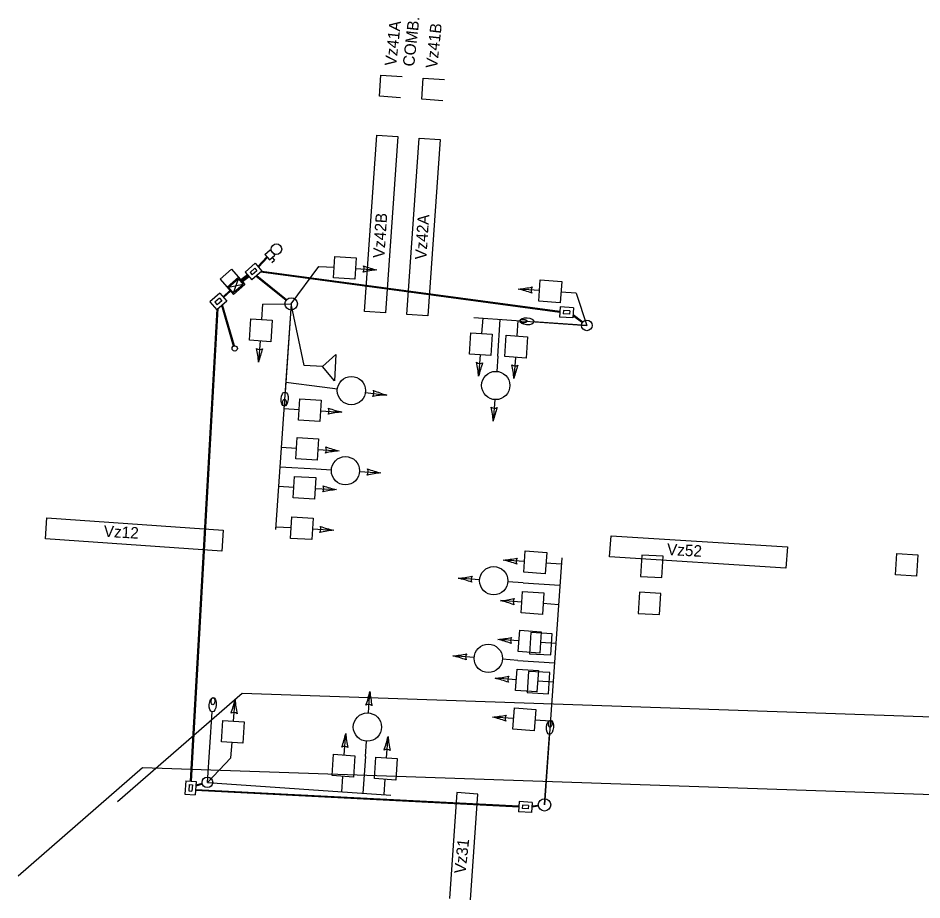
# Model space of a CAD drawing. Extents: x 647787 to 668496, y 640478 to 654412.
# Drawn here: x 661051 to 661306.8, y 647262.5 to 647511.9 of the extents above; entities that cross this region are included whole.
import ezdxf

# ---------------------------------------------------------------- set-up
doc = ezdxf.new("R2010")
doc.units = 0
for name, color, linetype in [('Default', 7, 'Continuous'), ('TEMP_DETECTION ZONE', 7, 'Continuous'), ('TEMP_DETECTION ZONE_STAGE 3', 7, 'Continuous'), ('TEMP_SIGNAL_HEAD_STAGE 1A', 7, 'Continuous'), ('TEMP_SIGNAL_POLES_STAGE 1A', 7, 'Continuous'), ('TEMP_SIGNAL_POLES_STAGE 1B', 7, 'Continuous'), ('TEXT_TEMP_SIGNAL_POLES_STAGE 5', 7, 'Continuous')]:
    doc.layers.add(name, color=color, linetype=linetype)

msp = doc.modelspace()

# ---------------------------------------------------------------- linework, layer by layer
at = {"layer": 'Default'}
for p, q in [((661114.4, 647320.89), (661079.2, 647290.26)), ((661086.25, 647299.89), (661051.05, 647269.26))]:
    msp.add_line(p, q, dxfattribs=at)
for points in [[(662136.44, 647331.77), (661882.02, 647294.61), (661114.4, 647320.89)], [(662108.29, 647310.77), (661853.87, 647273.61), (661086.25, 647299.89)]]:
    msp.add_lwpolyline(points, dxfattribs=at)
at = {"layer": 'TEMP_DETECTION ZONE'}
for points in [[(661227.5, 647359.98), (661227.14, 647354), (661233.13, 647353.68), (661233.5, 647359.67)], [(661227.5, 647359.98), (661227.14, 647354), (661233.13, 647353.68), (661233.5, 647359.67)], [(661226.87, 647349.5), (661226.51, 647343.51), (661232.5, 647343.2), (661232.86, 647349.19)], [(661226.87, 647349.5), (661226.51, 647343.51), (661232.5, 647343.2), (661232.86, 647349.19)]]:
    msp.add_lwpolyline(points, close=True, dxfattribs=at)
at = {"layer": 'TEMP_DETECTION ZONE_STAGE 3'}
for points in [[(661196.13, 647338.09), (661195.77, 647332.1), (661201.76, 647331.79), (661202.12, 647337.77)], [(661196.13, 647338.09), (661195.77, 647332.1), (661201.76, 647331.79), (661202.12, 647337.77)], [(661196.13, 647338.09), (661195.77, 647332.1), (661201.76, 647331.79), (661202.12, 647337.77)], [(661196.13, 647338.09), (661195.77, 647332.1), (661201.76, 647331.79), (661202.12, 647337.78)], [(661195.46, 647327.11), (661195.1, 647321.12), (661201.09, 647320.81), (661201.46, 647326.79)], [(661195.46, 647327.11), (661195.1, 647321.12), (661201.09, 647320.81), (661201.46, 647326.79)], [(661195.46, 647327.11), (661195.1, 647321.12), (661201.09, 647320.81), (661201.46, 647326.79)], [(661195.47, 647327.11), (661195.11, 647321.12), (661201.1, 647320.81), (661201.46, 647326.8)]]:
    msp.add_lwpolyline(points, close=True, dxfattribs=at)
at = {"layer": 'TEMP_SIGNAL_HEAD_STAGE 1A'}
for p, q in [((661120.84, 647444.99), (661122.35, 647446.31)), ((661122.35, 647446.31), (661123.66, 647444.8)), ((661118.89, 647441.61), (661121.41, 647444.34)), ((661119.05, 647441.42), (661121.58, 647444.15)), ((661120.84, 647444.99), (661122.15, 647443.49)), ((661122.15, 647443.49), (661123.66, 647444.8)), ((661122.81, 647442.73), (661123.56, 647443.39)), ((661122.91, 647444.14), (661123.56, 647443.39)), ((661118.09, 647442.53), (661115.26, 647440.07)), ((661117.99, 647441.12), (661116.67, 647439.97)), ((661120, 647440.33), (661117.17, 647437.87)), ((661118.59, 647440.43), (661117.27, 647439.28)), ((661117.99, 647441.12), (661118.59, 647440.43)), ((661118.09, 647442.53), (661120, 647440.33)), ((661119.97, 647440.31), (661204.34, 647428.98)), ((661115.94, 647439.29), (661114.09, 647437.83)), ((661116.1, 647439.1), (661114.25, 647437.64)), ((661116.26, 647438.91), (661114.42, 647437.45)), ((661116.43, 647438.72), (661114.58, 647437.26)), ((661115.26, 647440.07), (661117.17, 647437.87)), ((661116.67, 647439.97), (661117.27, 647439.28)), ((661118.38, 647438.92), (661126.87, 647432.06)), ((661118.57, 647439.09), (661127.03, 647432.26)), ((661119.72, 647440.09), (661204.33, 647428.73)), ((661108.16, 647434.07), (661105.33, 647431.61)), ((661108.06, 647432.66), (661106.74, 647431.51)), ((661108.06, 647432.66), (661108.67, 647431.96)), ((661108.16, 647434.07), (661110.08, 647431.87)), ((661110.98, 647434.81), (661109.03, 647433.07)), ((661111.06, 647434.71), (661109.11, 647432.98)), ((661111.14, 647434.62), (661109.19, 647432.88)), ((661105.33, 647431.61), (661107.25, 647429.41)), ((661106.74, 647431.51), (661107.35, 647430.82)), ((661110.08, 647431.87), (661107.25, 647429.41)), ((661108.67, 647431.96), (661107.35, 647430.82)), ((661112, 647419.13), (661108.66, 647430.63)), ((661112.24, 647419.2), (661108.87, 647430.81)), ((661204.43, 647430.24), (661204.23, 647427.33)), ((661208.17, 647429.98), (661204.43, 647430.24)), ((661208.17, 647429.98), (661207.97, 647427.07)), ((661099.82, 647296.08), (661107.4, 647429.54)), ((661100.07, 647296.07), (661107.66, 647429.77)), ((661205.36, 647429.17), (661205.3, 647428.26)), ((661207.04, 647428.14), (661205.3, 647428.26)), ((661207.11, 647429.05), (661205.36, 647429.17)), ((661207.11, 647429.05), (661207.04, 647428.14)), ((661208.02, 647427.74), (661210.68, 647425.76)), ((661208.04, 647428.04), (661210.83, 647425.96)), ((661207.97, 647427.07), (661204.23, 647427.33)), ((661098.5, 647296.18), (661098.24, 647292.44)), ((661098.5, 647296.18), (661101.41, 647295.97)), ((661099.43, 647295.11), (661099.31, 647293.36)), ((661099.43, 647295.11), (661100.35, 647295.05)), ((661100.35, 647295.05), (661100.22, 647293.3)), ((661101.41, 647295.97), (661101.15, 647292.23)), ((661103.2, 647295.23), (661101.32, 647294.7)), ((661103.13, 647295.47), (661101.34, 647294.97)), ((661098.24, 647292.44), (661101.15, 647292.23)), ((661099.31, 647293.36), (661100.22, 647293.3)), ((661192.67, 647288.77), (661101.24, 647293.43)), ((661192.69, 647289.02), (661101.25, 647293.68)), ((661192.78, 647290.36), (661192.58, 647287.45)), ((661196.52, 647290.1), (661192.78, 647290.36)), ((661196.52, 647290.1), (661196.32, 647287.19)), ((661196.32, 647287.19), (661192.58, 647287.45)), ((661193.71, 647289.3), (661193.65, 647288.38)), ((661195.39, 647288.26), (661193.65, 647288.38)), ((661195.46, 647289.18), (661193.71, 647289.3)), ((661195.46, 647289.18), (661195.39, 647288.26)), ((661198.27, 647289), (661196.43, 647288.74)), ((661198.24, 647289.25), (661196.45, 647288.99))]:
    msp.add_line(p, q, dxfattribs=at)
for centre, radius in [((661124.14, 647446.54), 1.5), ((661112.33, 647418.45), 0.75)]:
    msp.add_circle(centre, radius, dxfattribs=at)
at = {"layer": 'TEMP_SIGNAL_POLES_STAGE 1A'}
for p, q in [((661128.31, 647431.06), (661136.15, 647441.67)), ((661136.15, 647441.67), (661140.49, 647441.41)), ((661146.54, 647441.05), (661152.57, 647440.68)), ((661198.58, 647434.83), (661192.55, 647435.25)), ((661208.96, 647434.11), (661204.63, 647434.41)), ((661208.96, 647434.11), (661211.95, 647424.97)), ((661120.23, 647430.95), (661119.93, 647426.62)), ((661120.23, 647430.95), (661128.31, 647431.06)), ((661128.31, 647431.06), (661123.87, 647367.22)), ((661128.31, 647431.06), (661126.57, 647406.12)), ((661131.95, 647413.65), (661128.31, 647431.06)), ((661180.03, 647427.19), (661211.95, 647424.97)), ((661182.49, 647427.02), (661182.19, 647422.68)), ((661186.76, 647416.29), (661187.48, 647426.67)), ((661192.47, 647426.33), (661192.16, 647421.99)), ((661211.95, 647424.97), (661196.99, 647426.01)), ((661119.51, 647420.57), (661119.09, 647414.54)), ((661181.77, 647416.64), (661181.35, 647410.61)), ((661186.76, 647416.29), (661186.45, 647411.97)), ((661191.74, 647415.94), (661191.32, 647409.92)), ((661126.77, 647408.88), (661137.08, 647407.58)), ((661137.08, 647407.58), (661141.38, 647407.03)), ((661149.31, 647406.03), (661155.33, 647405.27)), ((661185.9, 647403.99), (661185.48, 647397.94)), ((661126.25, 647401.46), (661130.59, 647401.2)), ((661136.64, 647400.84), (661142.67, 647400.47)), ((661125.49, 647390.49), (661129.83, 647390.23)), ((661135.88, 647389.86), (661141.91, 647389.5)), ((661125.06, 647385.01), (661135.36, 647384.38)), ((661135.36, 647384.38), (661139.68, 647384.12)), ((661147.67, 647383.64), (661153.72, 647383.28)), ((661124.72, 647379.52), (661129.06, 647379.25)), ((661135.12, 647378.89), (661141.14, 647378.53)), ((661123.93, 647368.04), (661128.27, 647367.78)), ((661134.32, 647367.42), (661140.35, 647367.05)), ((661194.33, 647358.18), (661188.31, 647358.6)), ((661204.72, 647357.46), (661200.38, 647357.76)), ((661181.62, 647353.05), (661175.57, 647353.47)), ((661193.92, 647352.19), (661189.6, 647352.49)), ((661193.92, 647352.19), (661204.3, 647351.47)), ((661193.54, 647346.71), (661187.51, 647347.13)), ((661203.92, 647345.98), (661199.58, 647346.29)), ((661192.77, 647335.73), (661186.75, 647336.15)), ((661203.16, 647335.01), (661198.82, 647335.31)), ((661180.09, 647331.1), (661174.04, 647331.52)), ((661192.39, 647330.25), (661188.07, 647330.55)), ((661192.39, 647330.25), (661202.78, 647329.52)), ((661192.01, 647324.76), (661185.98, 647325.18)), ((661202.39, 647324.04), (661198.06, 647324.34)), ((661150.17, 647315.38), (661150.59, 647321.43)), ((661112, 647313.07), (661112.42, 647319.09)), ((661104.6, 647295.75), (661105.99, 647315.7)), ((661191.25, 647313.79), (661185.22, 647314.2)), ((661201.63, 647313.06), (661197.3, 647313.37)), ((661143.33, 647303.5), (661143.75, 647309.52)), ((661149.31, 647303.08), (661149.61, 647307.4)), ((661155.3, 647302.66), (661155.72, 647308.69)), ((661199.98, 647289.37), (661201.37, 647309.32)), ((661111.28, 647302.68), (661111.58, 647307.02)), ((661111.28, 647302.68), (661104.6, 647295.75)), ((661149.31, 647303.08), (661148.59, 647292.69)), ((661142.61, 647293.11), (661142.91, 647297.45)), ((661104.6, 647295.75), (661156.48, 647292.15)), ((661154.58, 647292.28), (661154.88, 647296.61))]:
    msp.add_line(p, q, dxfattribs=at)
for points in [[(661140.31, 647438.38), (661140.68, 647444.44), (661146.73, 647444.07), (661146.36, 647438.02)], [(661204.84, 647437.43), (661204.42, 647431.38), (661198.37, 647431.8), (661198.79, 647437.85)], [(661116.9, 647426.83), (661122.95, 647426.41), (661122.53, 647420.36), (661116.48, 647420.78)], [(661179.16, 647422.89), (661185.21, 647422.47), (661184.79, 647416.42), (661178.74, 647416.85)], [(661189.14, 647422.2), (661195.19, 647421.78), (661194.77, 647415.73), (661188.72, 647416.15)], [(661130.41, 647398.18), (661130.77, 647404.23), (661136.82, 647403.86), (661136.46, 647397.81)], [(661129.64, 647387.2), (661130.01, 647393.26), (661136.06, 647392.89), (661135.7, 647386.84)], [(661128.88, 647376.23), (661129.25, 647382.28), (661135.3, 647381.92), (661134.93, 647375.86)], [(661128.08, 647364.75), (661128.45, 647370.81), (661134.5, 647370.44), (661134.13, 647364.39)], [(661200.59, 647360.78), (661200.17, 647354.73), (661194.12, 647355.15), (661194.54, 647361.2)], [(661199.79, 647349.31), (661199.37, 647343.26), (661193.33, 647343.68), (661193.75, 647349.73)], [(661199.03, 647338.34), (661198.61, 647332.29), (661192.56, 647332.71), (661192.98, 647338.76)], [(661198.27, 647327.36), (661197.85, 647321.31), (661191.8, 647321.73), (661192.22, 647327.78)], [(661197.51, 647316.39), (661197.09, 647310.34), (661191.04, 647310.76), (661191.46, 647316.81)], [(661114.61, 647306.81), (661108.56, 647307.23), (661108.98, 647313.28), (661115.03, 647312.86)], [(661145.93, 647297.24), (661139.88, 647297.66), (661140.3, 647303.71), (661146.35, 647303.28)], [(661157.9, 647296.4), (661151.85, 647296.82), (661152.27, 647302.87), (661158.32, 647302.45)]]:
    msp.add_lwpolyline(points, close=True, dxfattribs=at)
for points in [[(661137.16, 647413.33), (661140.97, 647416.71), (661140.53, 647409.34), (661137.16, 647413.33), (661131.95, 647413.65)], [(661204.84, 647359.2), (661199.98, 647289.37)]]:
    msp.add_lwpolyline(points, dxfattribs=at)
for centre, radius in [((661128.31, 647431.06), 1.75), ((661211.95, 647424.97), 1.5), ((661145.35, 647406.53), 4), ((661186.18, 647407.98), 4), ((661143.67, 647383.88), 4), ((661185.61, 647352.77), 4), ((661184.08, 647330.82), 4), ((661149.89, 647311.39), 4), ((661104.6, 647295.75), 1.5), ((661199.98, 647289.37), 1.75)]:
    msp.add_circle(centre, radius, dxfattribs=at)
for centre, radius, start, end in [((661147.32, 647441), 1.63, 324.7005, 28.3952), ((661155.22, 647411.33), 29.47, 95.1562, 102.8943), ((661158.73, 647469.5), 29.47, 250.2014, 257.9395), ((661190.17, 647464.62), 29.47, 274.634, 282.3721), ((661186.13, 647406.48), 29.47, 69.6792, 77.4173), ((661197.81, 647434.88), 1.63, 144.1783, 207.873), ((661119.45, 647419.8), 1.63, 234.1757, 297.8704), ((661089.71, 647412.16), 29.47, 4.6314, 12.3695), ((661147.85, 647408.12), 29.47, 159.6766, 167.4147), ((661181.71, 647415.86), 1.63, 234.1757, 297.8704), ((661151.97, 647408.23), 29.47, 4.6314, 12.3695), ((661210.11, 647404.19), 29.47, 159.6766, 167.4147), ((661191.69, 647415.17), 1.63, 234.1757, 297.8704), ((661161.95, 647407.54), 29.47, 4.6314, 12.3695), ((661220.09, 647403.49), 29.47, 159.6766, 167.4147), ((661150.11, 647405.93), 1.63, 320.9402, 24.6348), ((661156.05, 647375.81), 29.47, 91.4068, 99.1449), ((661163.36, 647433.62), 29.47, 246.4511, 254.1893), ((661185.84, 647403.19), 1.63, 234.1757, 297.8704), ((661156.1, 647395.55), 29.47, 4.6424, 12.3805), ((661137.41, 647400.79), 1.63, 324.7005, 28.3952), ((661145.32, 647371.12), 29.47, 95.1562, 102.8943), ((661148.83, 647429.29), 29.47, 250.2014, 257.9395), ((661214.24, 647391.52), 29.47, 159.6867, 167.4248), ((661136.65, 647389.82), 1.63, 324.7005, 28.3952), ((661144.56, 647360.15), 29.47, 95.1562, 102.8943), ((661148.07, 647418.32), 29.47, 250.2014, 257.9395), ((661148.46, 647383.59), 1.63, 324.6979, 28.3925), ((661159.87, 647412.1), 29.47, 250.2089, 257.947), ((661156.37, 647353.92), 29.47, 95.1646, 102.9027), ((661135.89, 647378.84), 1.63, 324.7005, 28.3952), ((661147.3, 647407.35), 29.47, 250.2014, 257.9395), ((661143.79, 647349.17), 29.47, 95.1562, 102.8943), ((661135.09, 647367.37), 1.63, 324.7005, 28.3952), ((661143, 647337.7), 29.47, 95.1562, 102.8943), ((661146.51, 647395.87), 29.47, 250.2014, 257.9395), ((661185.93, 647387.97), 29.47, 274.634, 282.3721), ((661181.89, 647329.83), 29.47, 69.6792, 77.4173), ((661193.56, 647358.23), 1.63, 144.1783, 207.873), ((661173.18, 647382.84), 29.47, 274.6424, 282.3805), ((661169.15, 647324.71), 29.47, 69.6867, 77.4248), ((661180.82, 647353.1), 1.63, 144.1757, 207.8704), ((661185.13, 647376.5), 29.47, 274.634, 282.3721), ((661181.09, 647318.36), 29.47, 69.6792, 77.4173), ((661192.76, 647346.76), 1.63, 144.1783, 207.873), ((661184.37, 647365.53), 29.47, 274.634, 282.3721), ((661180.33, 647307.39), 29.47, 69.6792, 77.4173), ((661192, 647335.79), 1.63, 144.1783, 207.873), ((661171.66, 647360.9), 29.47, 274.6424, 282.3805), ((661167.62, 647302.76), 29.47, 69.6867, 77.4248), ((661179.29, 647331.16), 1.63, 144.1757, 207.8704), ((661183.6, 647354.55), 29.47, 274.634, 282.3721), ((661179.56, 647296.41), 29.47, 69.6792, 77.4173), ((661191.24, 647324.81), 1.63, 144.1783, 207.873), ((661121.83, 647327.85), 29.47, 339.6867, 347.4248), ((661179.96, 647323.81), 29.47, 184.6424, 192.3805), ((661083.66, 647325.52), 29.47, 339.6766, 347.4147), ((661141.8, 647321.47), 29.47, 184.6314, 192.3695), ((661150.22, 647316.18), 1.63, 54.1757, 117.8704), ((661112.06, 647313.84), 1.63, 54.1757, 117.8704), ((661182.84, 647343.58), 29.47, 274.634, 282.3721), ((661178.8, 647285.44), 29.47, 69.6792, 77.4173), ((661190.47, 647313.84), 1.63, 144.1783, 207.873), ((661114.98, 647315.94), 29.47, 339.6766, 347.4147), ((661173.12, 647311.9), 29.47, 184.6314, 192.3695), ((661126.95, 647315.11), 29.47, 339.6766, 347.4147), ((661185.09, 647311.07), 29.47, 184.6314, 192.3695), ((661143.38, 647304.27), 1.63, 54.1757, 117.8704), ((661155.35, 647303.43), 1.63, 54.1757, 117.8704)]:
    msp.add_arc(centre, radius, start, end, dxfattribs=at)
for centre, major_axis in [((661194.99, 647426.15), (-2, 0.14)), ((661194, 647426.22), (0.998, -0.069)), ((661126.44, 647404.13), (-0.14, -2)), ((661126.37, 647403.13), (0.069, 0.998)), ((661106.13, 647317.7), (0.14, 2)), ((661106.2, 647318.7), (-0.069, -0.998)), ((661201.51, 647311.32), (0.14, 2)), ((661201.58, 647312.32), (-0.069, -0.998))]:
    msp.add_ellipse(centre, major_axis=major_axis, ratio=0.5, dxfattribs=at)
at = {"layer": 'TEMP_SIGNAL_POLES_STAGE 1B'}
for p, q in [((661153.27, 647489.77), (661153.69, 647495.75)), ((661153.69, 647495.75), (661159.67, 647495.33)), ((661165.24, 647488.93), (661165.66, 647494.92)), ((661165.66, 647494.92), (661171.64, 647494.5)), ((661159.26, 647489.35), (661153.27, 647489.77)), ((661171.23, 647488.52), (661165.24, 647488.93)), ((661149.04, 647428.91), (661152.51, 647478.79)), ((661152.51, 647478.79), (661158.49, 647478.38)), ((661158.49, 647478.38), (661155.03, 647428.5)), ((661161.01, 647428.08), (661164.48, 647477.96)), ((661164.48, 647477.96), (661170.46, 647477.54)), ((661170.46, 647477.54), (661167, 647427.66)), ((661155.03, 647428.5), (661149.04, 647428.91)), ((661167, 647427.66), (661161.01, 647428.08)), ((661058.77, 647364.6), (661059.18, 647370.58)), ((661059.18, 647370.58), (661109.06, 647367.11)), ((661109.06, 647367.11), (661108.65, 647361.13)), ((661108.65, 647361.13), (661058.77, 647364.6)), ((661218.39, 647359.51), (661218.81, 647365.5)), ((661218.81, 647365.5), (661268.71, 647362.31)), ((661268.71, 647362.31), (661268.29, 647356.32)), ((661268.29, 647356.32), (661218.39, 647359.51)), ((661299.24, 647354.45), (661299.65, 647360.44)), ((661299.65, 647360.44), (661305.64, 647360.08)), ((661305.64, 647360.08), (661305.23, 647354.09)), ((661305.23, 647354.09), (661299.24, 647354.45)), ((661175.17, 647292.85), (661173.09, 647262.92)), ((661181.15, 647292.44), (661175.17, 647292.85)), ((661179.07, 647262.51), (661181.15, 647292.44))]:
    msp.add_line(p, q, dxfattribs=at)
at = {"layer": 'TEXT_TEMP_SIGNAL_POLES_STAGE 5'}
for p, q in [((661111.45, 647440.86), (661108.19, 647438.01)), ((661111.45, 647440.86), (661115.22, 647436.52)), ((661108.19, 647438.01), (661111.96, 647433.68)), ((661113.42, 647438.59), (661110.16, 647435.75)), ((661113.39, 647438.13), (661110.62, 647435.72)), ((661111.99, 647434.15), (661113.39, 647438.12)), ((661113.39, 647438.13), (661114.76, 647436.56)), ((661114.74, 647436.54), (661110.62, 647435.72)), ((661110.62, 647435.72), (661111.99, 647434.15)), ((661115.22, 647436.52), (661111.96, 647433.68)), ((661114.76, 647436.56), (661111.99, 647434.15))]:
    msp.add_line(p, q, dxfattribs=at)

# ---------------------------------------------------------------- texts
at = {"layer": 'TEMP_SIGNAL_POLES_STAGE 1B'}
for s, rotation, p in [('COMB.', 83.6315, (661163.08, 647498.05)), ('Vz41A', 83.6315, (661157.97, 647498.19)), ('Vz41B', 83.6315, (661169.55, 647497.53)), ('Vz42B', 86.2331, (661154.66, 647443.91)), ('Vz42A', 86.2331, (661166.54, 647443.47)), ('Vz12', 356.7697, (661075.21, 647365.19)), ('Vz52', 356.7697, (661234.55, 647360.07)), ('Vz31', 83.7849, (661177.62, 647269.79))]:
    msp.add_text(s, height=3.25, rotation=rotation, dxfattribs=at).set_placement(p)

doc.saveas('drawing.dxf')
